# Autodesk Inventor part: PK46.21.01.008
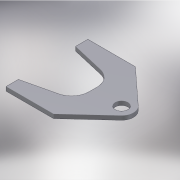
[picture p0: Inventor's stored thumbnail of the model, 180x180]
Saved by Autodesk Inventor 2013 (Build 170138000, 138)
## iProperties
Created: 2005-04
Part Number: PK46.21.01.008
Material: Steel, Mild
Document SubType Name: Modeling
Designer: salex
Manufacturer: Standard
Standards Organization: Custom
Density: 7.86 g/cm^3
Author: salex
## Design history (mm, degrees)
sketch "Эскиз1"
  geometry: L1 (-280, -40.1)-(-280, 40.1); L2 (-411.371, 205.653)-(-730, 280); L3 (-730, 280)-(-730, 400); L4 (-730, 400)-(-265, 400); L5 (-265, 400)-(77.853, 84.64); L6 (0, 0)-(-506.787, 0); L7 (-730, -400)-(-265, -400); L8 (-730, -280)-(-730, -400); L9 (-411.371, -205.653)-(-730, -280); L10 (-265, -400)-(77.853, -84.64); L11 (-411.371, 205.653)-(-280, 175); L12 (-280, 175)-(-280, 40.1); C1 r 62.5 at (0, 0); A1 r 115 centre (0, 0) between (77.853, -84.64) and (77.853, 84.64); A2 r 170 centre (-450, 40.1) between (-280, 40.1) and (-411.371, 205.653); A3 r 170 centre (-450, -40.1) between (-411.371, -205.653) and (-280, -40.1)
  constraints: 24 end point, 7 symmetric about line, 6 point on circle, 4 centre point, 4 tangent, 3 parallel, 1 coincident, 1 collinear, 1 perpendicular, 1 vertical, 2 other
  dimensions: "d0" = 115 radius of A1; "d1" = 125 diameter of C1; "d2" = 800 distance between parallel lines of L7 L4; "d3" = 265 horizontal distance of C1.centre L4.end; "d4" = 730 distance from line of L8 C1.centre; "d5" = 120 distance of L2.end L3.end; "d6" = 170 radius of A2; "d7" = 280 distance from line of C1.centre L1; "d8" = 225 distance from line of L11.end L4
extrude "Выдавливание1" new body sketch "Эскиз1" distance "d9" = 40; taper "d10" = 0 deg
body "Solid1"
